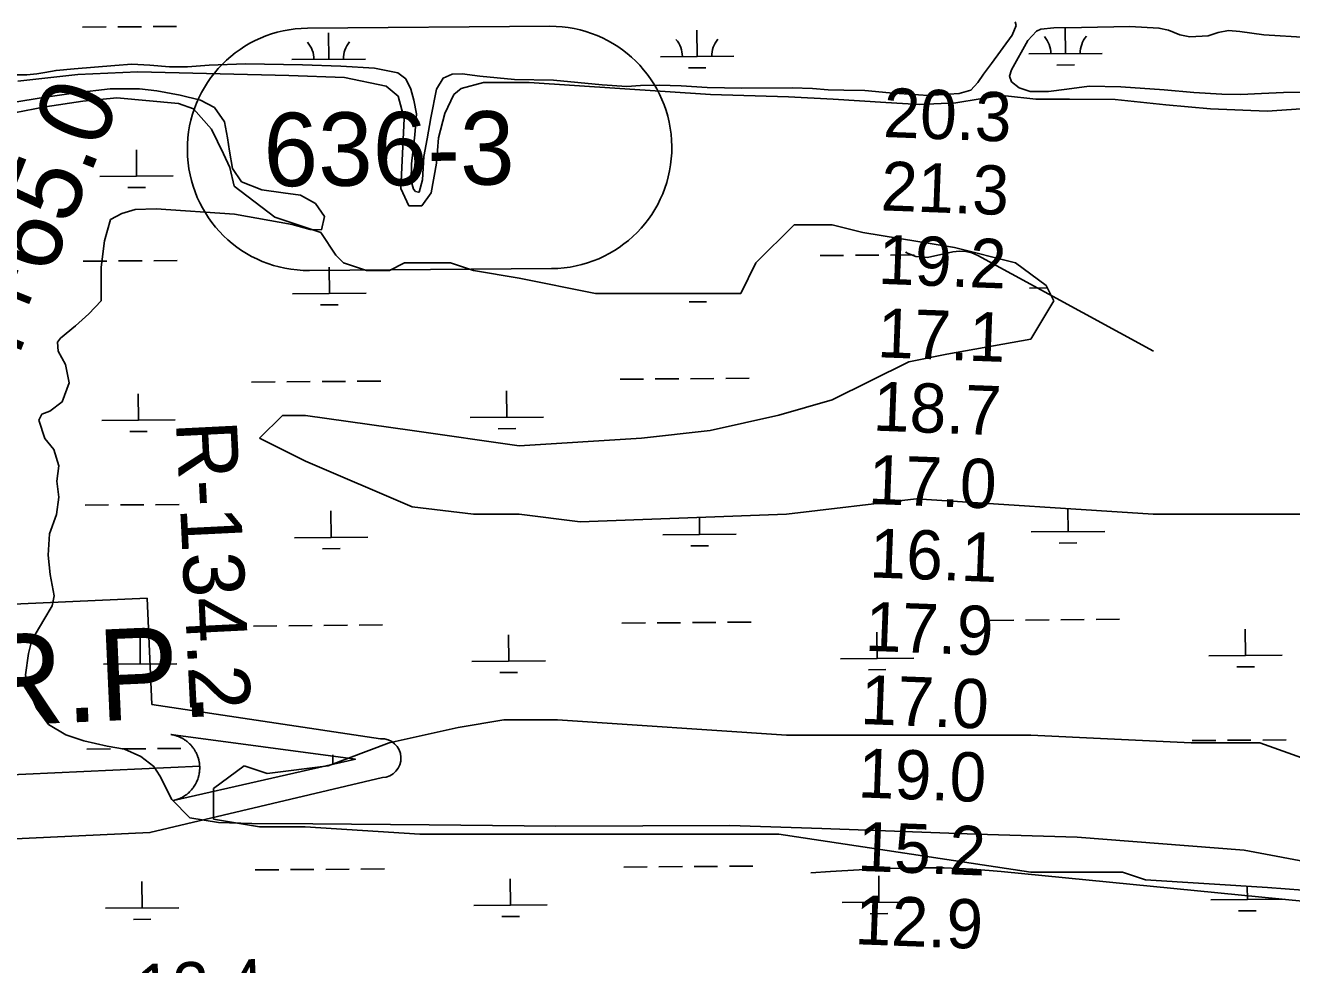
# Model space of a CAD drawing. Extents: x 3540316 to 3578335, y 553172 to 578787.
# Drawn here: x 3545537 to 3547262, y 567214 to 568493 of the extents above; entities that cross this region are included whole.
import ezdxf

# ---------------------------------------------------------------- set-up
doc = ezdxf.new("R2010")
doc.units = 0
for name, color, linetype in [('V-RIVR-RANG', 7, 'Continuous'), ('V-RIVR-RANG-IDEN', 7, 'Continuous'), ('V-ROAD-IDEN', 7, 'Continuous'), ('V-SITE-VEGE', 7, 'Continuous'), ('V-SURV-IDEN', 7, 'Continuous'), ('V-TOPO-MINR', 7, 'Continuous'), ('V-TOPO-WATR-IDEN', 7, 'Continuous'), ('V-WETL-SWMP', 7, 'Continuous')]:
    doc.layers.add(name, color=color, linetype=linetype)

msp = doc.modelspace()

# ---------------------------------------------------------------- linework, layer by layer
at = {"layer": 'V-ROAD-IDEN'}
for p, q in [((3545921.8, 568489.1), (3546251.8, 568491.7)), ((3545921.8, 568489.1), (3546251.8, 568491.7)), ((3545921.8, 568489.1), (3545921.8, 568489.1)), ((3546254.3, 568161.7), (3545924.3, 568159.1)), ((3546254.3, 568161.7), (3545924.3, 568159.1))]:
    msp.add_line(p, q, dxfattribs=at)
for centre, start, end in [((3546253.1, 568326.7), 270.4418, 90.4418), ((3546253.1, 568326.7), 270.4418, 90.4418), ((3545923.1, 568324.1), 90.4418, 270.4418), ((3545923.1, 568324.1), 90.4418, 270.4418)]:
    msp.add_arc(centre, 165, start, end, dxfattribs=at)
at = {"layer": 'V-SITE-VEGE'}
for p, q in [((3545527.3, 568416.9), (3545608.9, 568426.2)), ((3545608.9, 568426.2), (3545690.4, 568429.9)), ((3545690.4, 568429.9), (3545896.2, 568424.9)), ((3545896.2, 568424.9), (3545972.2, 568421.8)), ((3545972.2, 568421.8), (3546028.8, 568410.4)), ((3545653, 568406.6), (3545606, 568401.3)), ((3545693.1, 568406.4), (3545653, 568406.6)), ((3545716.5, 568403.6), (3545693.1, 568406.4)), ((3545748.3, 568397.9), (3545716.5, 568403.6)), ((3546028.8, 568410.4), (3546045.3, 568396.6)), ((3546121.3, 568399), (3546131, 568407.2)), ((3546131, 568407.2), (3546161.4, 568415.4)), ((3546161.4, 568415.4), (3546223.6, 568415.1)), ((3546223.6, 568415.1), (3546470.7, 568398.8)), ((3545561.8, 568394.6), (3545520.3, 568387.9)), ((3545606, 568401.3), (3545561.8, 568394.6)), ((3545775.9, 568390.9), (3545748.3, 568397.9)), ((3545795.2, 568381.1), (3545775.9, 568390.9)), ((3546045.3, 568396.6), (3546053.4, 568366.1)), ((3546108.7, 568372.8), (3546121.3, 568399)), ((3546470.7, 568398.8), (3546577.1, 568395.5)), ((3546577.1, 568395.5), (3546637.9, 568392.5)), ((3546637.9, 568392.5), (3546709.7, 568388)), ((3546709.7, 568388), (3546755.2, 568385)), ((3546755.2, 568385), (3546805, 568387.6)), ((3546805, 568387.6), (3546838.2, 568392.9)), ((3546838.2, 568392.9), (3546854.7, 568395.6)), ((3546854.7, 568395.6), (3546872.7, 568396.9)), ((3546872.7, 568396.9), (3546914.1, 568392.6)), ((3546914.1, 568392.6), (3546959.7, 568392.4)), ((3546959.7, 568392.4), (3547021.9, 568392.1)), ((3547021.9, 568392.1), (3547090.9, 568384.9)), ((3545808.9, 568361.7), (3545795.2, 568381.1)), ((3546100.3, 568339.7), (3546108.7, 568372.8)), ((3547090.9, 568384.9), (3547151.7, 568379.1)), ((3547151.7, 568379.1), (3547229, 568376)), ((3547229, 568376), (3547302.2, 568381.2)), ((3545812.9, 568339.6), (3545808.9, 568361.7)), ((3546053.4, 568366.1), (3546048.8, 568270.8)), ((3545815.6, 568321.6), (3545812.9, 568339.6)), ((3546097.3, 568305.1), (3546100.3, 568339.7)), ((3545819.7, 568298.1), (3545815.6, 568321.6)), ((3546090.3, 568265.1), (3546097.3, 568305.1)), ((3545832, 568280.1), (3545819.7, 568298.1)), ((3545859.6, 568268.9), (3545832, 568280.1)), ((3545888.6, 568264.7), (3545859.6, 568268.9)), ((3546048.8, 568270.8), (3546059.8, 568247.3)), ((3546077.7, 568247.2), (3546090.3, 568265.1)), ((3545912, 568261.8), (3545888.6, 568264.7)), ((3545932.7, 568250.6), (3545912, 568261.8)), ((3545945.1, 568232.6), (3545932.7, 568250.6)), ((3545653.6, 568228.4), (3545668.8, 568236.6)), ((3545668.8, 568236.6), (3545686.8, 568242.1)), ((3545686.8, 568242.1), (3545715.8, 568243.3)), ((3545715.8, 568243.3), (3545822.1, 568235.9)), ((3545822.1, 568235.9), (3545900.8, 568221.8)), ((3545940.8, 568214.7), (3545945.1, 568232.6)), ((3546059.8, 568247.3), (3546077.7, 568247.2)), ((3545645.2, 568199.5), (3545653.6, 568228.4)), ((3545900.8, 568221.8), (3545925.6, 568214.8)), ((3545925.6, 568214.8), (3545940.8, 568214.7)), ((3545640.8, 568163.6), (3545645.2, 568199.5)), ((3545640.8, 568142.8), (3545640.8, 568163.6)), ((3545640.6, 568118), (3545640.8, 568142.8)), ((3545624, 568100.1), (3545640.6, 568118)), ((3545605.9, 568083.6), (3545624, 568100.1)), ((3545585.2, 568067.1), (3545605.9, 568083.6)), ((3545581, 568061.6), (3545585.2, 568067.1)), ((3545582.3, 568049.2), (3545581, 568061.6)), ((3545591.9, 568031.2), (3545582.3, 568049.2)), ((3545597.3, 568006.3), (3545591.9, 568031.2)), ((3545587.5, 567980.1), (3545597.3, 568006.3)), ((3545570.9, 567967.7), (3545587.5, 567980.1)), ((3545555.6, 567955.4), (3545559.8, 567963.6)), ((3545563.8, 567930.5), (3545555.6, 567955.4)), ((3545559.8, 567963.6), (3545570.9, 567967.7)), ((3545576.2, 567915.2), (3545563.8, 567930.5)), ((3545583, 567893.1), (3545576.2, 567915.2)), ((3545580.1, 567872.4), (3545583, 567893.1)), ((3545582.8, 567850.3), (3545580.1, 567872.4)), ((3545579.9, 567826.8), (3545582.8, 567850.3)), ((3545570.1, 567800.6), (3545579.9, 567826.8)), ((3545568.6, 567771.6), (3545570.1, 567800.6)), ((3545571.3, 567745.3), (3545568.6, 567771.6)), ((3545576.6, 567716.3), (3545571.3, 567745.3)), ((3545573.8, 567702.5), (3545576.6, 567716.3)), ((3545562.7, 567683.2), (3545573.8, 567702.5)), ((3545546, 567655.7), (3545562.7, 567683.2)), ((3545541.8, 567637.7), (3545546, 567655.7)), ((3545537.5, 567608.7), (3545541.8, 567637.7)), ((3545541.5, 567589.4), (3545537.5, 567608.7)), ((3545552.5, 567563.1), (3545541.5, 567589.4)), ((3545568.9, 567540.9), (3545552.5, 567563.1)), ((3545592.4, 567527), (3545568.9, 567540.9)), ((3545617.2, 567518.6), (3545592.4, 567527)), ((3545648.9, 567511.5), (3545617.2, 567518.6)), ((3545672.4, 567507.3), (3545648.9, 567511.5)), ((3545694.5, 567497.5), (3545672.4, 567507.3)), ((3545712.3, 567483.6), (3545694.5, 567497.5)), ((3545720.6, 567471.1), (3545712.3, 567483.6)), ((3545737, 567438.6), (3545720.6, 567471.1)), ((3545761.3, 567413.8), (3545737, 567438.6)), ((3545800.6, 567407.6), (3545761.3, 567413.8)), ((3545845.7, 567406.2), (3545800.6, 567407.6)), ((3545929.2, 567405.4), (3545845.7, 567406.2)), ((3546087.3, 567404), (3545929.2, 567405.4)), ((3546260.2, 567402.5), (3546087.3, 567404)), ((3546496.9, 567403.3), (3546260.2, 567402.5)), ((3546622.6, 567399.2), (3546496.9, 567403.3)), ((3546832.7, 567391.5), (3546622.6, 567399.2)), ((3546970.2, 567387.3), (3546832.7, 567391.5)), ((3547197.9, 567369.6), (3546970.2, 567387.3)), ((3547309.7, 567348.9), (3547197.9, 567369.6))]:
    msp.add_line(p, q, dxfattribs=at)
at = {"layer": 'V-TOPO-MINR'}
for points in [[(3547074, 568049.1), (3546835, 568179.6), (3546826.8, 568183), (3546818.4, 568185.2), (3546809.8, 568185.5), (3546800.9, 568184.5), (3546766.2, 568177), (3546750.6, 568178.2), (3546737.8, 568183.3), (3546736.9, 568184.4)], [(3548007.1, 567208.3), (3547986.8, 567215.2), (3547966.4, 567221.5), (3547945.6, 567227), (3547924.7, 567231.9), (3547903.7, 567235.9), (3547882.5, 567239.5), (3547861.3, 567242.5), (3547840, 567244.9), (3546866.5, 567340.8), (3546827.9, 567343.8), (3546789.2, 567345.7), (3546750.5, 567345.8), (3546711.8, 567344.9), (3546673.1, 567342.9), (3546634.4, 567340.7), (3546607.3, 567338.8)]]:
    msp.add_lwpolyline(points, dxfattribs=at)
at = {"layer": 'V-TOPO-WATR-IDEN'}
msp.add_line((3545024.4, 567450.2), (3545774.9, 567483.9), dxfattribs=at)
for points in [[(3544775.5, 567465.6), (3545071.8, 567539.6), (3545065.4, 567684.2), (3545703.2, 567712.9), (3545709.7, 567568.3), (3546021.4, 567521.5)], [(3546023.8, 567468.6), (3545707, 567393.6), (3545503.8, 567384.4), (3545510.7, 567229.3), (3545321.8, 567220.8), (3545314.9, 567376), (3545090.3, 567365.9), (3544777.9, 567412.6)]]:
    msp.add_lwpolyline(points, dxfattribs=at)
msp.add_lwpolyline([(3545735.4, 567527.2), (3545987, 567493.5), (3545739.4, 567437.3), (3545743.8, 567438.5), (3545747.9, 567440.1), (3545749.5, 567440.9), (3545750.9, 567441.6), (3545752.6, 567442.6), (3545754.1, 567443.5), (3545755.4, 567444.4), (3545757.2, 567445.7), (3545759, 567447.2), (3545759.9, 567448), (3545761.2, 567449.2), (3545762.7, 567450.8), (3545763.9, 567452.1), (3545765, 567453.5), (3545765.8, 567454.4), (3545766.6, 567455.5), (3545767.5, 567456.9), (3545768.3, 567458.2), (3545769, 567459.5), (3545769.6, 567460.5), (3545770.5, 567462.2), (3545771.2, 567463.8), (3545771.7, 567465.1), (3545772.3, 567466.6), (3545772.8, 567468), (3545773.1, 567469.2), (3545773.4, 567470.2), (3545773.7, 567471.6), (3545774.1, 567473.1), (3545774.3, 567474.6), (3545774.5, 567476.1), (3545774.7, 567477.4), (3545774.8, 567478.9), (3545774.9, 567480.2), (3545774.9, 567481.9), (3545774.9, 567483.9), (3545774.8, 567484.6), (3545774.8, 567485.5), (3545774.7, 567486.6), (3545774.5, 567487.6), (3545774.4, 567488.7), (3545774.2, 567489.7), (3545774, 567490.8), (3545773.9, 567491.6), (3545773.6, 567492.8), (3545773.3, 567493.9), (3545773.1, 567494.7), (3545772.5, 567496.6), (3545772.1, 567497.6), (3545771.9, 567498.3), (3545771.4, 567499.4), (3545771, 567500.4), (3545770.5, 567501.5), (3545769.9, 567502.7), (3545769.3, 567503.8), (3545768.8, 567504.7), (3545768.4, 567505.4), (3545767.8, 567506.4), (3545767.2, 567507.2), (3545766.6, 567508.2), (3545765.9, 567509.2), (3545765.1, 567510.2), (3545764.1, 567511.4), (3545763.4, 567512.2), (3545762.6, 567513.1), (3545761.7, 567514), (3545761.1, 567514.7), (3545760.3, 567515.4), (3545759.1, 567516.4), (3545759.1, 567516.5), (3545758.4, 567517.1), (3545757.8, 567517.5), (3545757, 567518.2), (3545756, 567518.9), (3545755.1, 567519.5), (3545754.4, 567520), (3545753.4, 567520.7), (3545752.4, 567521.3), (3545751.7, 567521.7), (3545750.8, 567522.2), (3545749.5, 567522.9), (3545748.7, 567523.2), (3545748.1, 567523.5), (3545747.5, 567523.8), (3545746.8, 567524.1), (3545745.9, 567524.4), (3545745, 567524.8), (3545744.1, 567525.1), (3545743.2, 567525.4), (3545742, 567525.8), (3545741.3, 567526), (3545740.1, 567526.3), (3545738.8, 567526.6), (3545737.8, 567526.8), (3545737, 567526.9), (3545736.3, 567527.1), (3545735.7, 567527.1)], close=True, dxfattribs=at)
msp.add_arc((3546022.6, 567495), 26.5, 272.5722, 92.5722, dxfattribs=at)
at = {"layer": 'V-WETL-SWMP'}
for p, q in [((3545615.4, 568490.5), (3545647.4, 568490.8)), ((3545663.4, 568490.9), (3545695.4, 568491.1)), ((3545711.4, 568491.3), (3545743.4, 568491.5)), ((3546954.4, 568454.4), (3546954.1, 568490)), ((3545950.6, 568446.7), (3545950.3, 568482.7)), ((3546452.5, 568450.5), (3546452.2, 568486.5)), ((3546904.4, 568454), (3547004.4, 568454.8)), ((3545900.6, 568446.3), (3546000.6, 568447.1)), ((3546402.5, 568450.2), (3546502.5, 568450.9)), ((3546942.5, 568438.9), (3546966.5, 568439.1)), ((3546440.6, 568435), (3546464.6, 568435.2)), ((3545564.5, 568382.2), (3545615.8, 568389.6)), ((3545615.8, 568389.6), (3545662.2, 568394.1)), ((3545662.2, 568394.1), (3545745.9, 568386.5)), ((3545745.9, 568386.5), (3545766.5, 568379.4)), ((3545522.1, 568373.7), (3545564.5, 568382.2)), ((3545766.5, 568379.4), (3545790.9, 568351.7)), ((3545790.9, 568351.7), (3545807.3, 568318.2)), ((3545688.9, 568287.5), (3545688.6, 568323.5)), ((3545807.3, 568318.2), (3545816, 568299.4)), ((3545816, 568299.4), (3545821.7, 568273.9)), ((3545638.9, 568287.1), (3545738.9, 568287.9)), ((3545677, 568272), (3545701, 568272.2)), ((3545821.7, 568273.9), (3545877.3, 568231.6)), ((3545877.3, 568231.6), (3545939.7, 568210.9)), ((3546532.7, 568169.5), (3546584.7, 568221.4)), ((3546584.7, 568221.4), (3546636.7, 568221.4)), ((3546636.7, 568221.4), (3546678.3, 568211)), ((3545939.7, 568210.9), (3545960.5, 568179.8)), ((3546678.3, 568211), (3546803.2, 568190.3)), ((3545960.5, 568179.8), (3545970.9, 568169.4)), ((3546620.1, 568179.4), (3546652.1, 568179.7)), ((3546668.1, 568179.8), (3546700.1, 568180.1)), ((3546716.1, 568180.2), (3546748.1, 568180.4)), ((3546803.2, 568190.3), (3546886.4, 568169.6)), ((3545616.3, 568171.7), (3545648.3, 568171.9)), ((3545664.3, 568172.1), (3545696.3, 568172.3)), ((3545712.3, 568172.4), (3545744.3, 568172.7)), ((3545951.5, 568127.9), (3545951.2, 568163.9)), ((3545970.9, 568169.4), (3546002.1, 568159)), ((3546033.3, 568159), (3546054.1, 568169.4)), ((3546054.1, 568169.4), (3546116.5, 568169.4)), ((3546116.5, 568169.4), (3546147.7, 568159.1)), ((3546511.9, 568128), (3546532.7, 568169.5)), ((3546886.4, 568169.6), (3546928, 568138.5)), ((3546002.1, 568159), (3546033.3, 568159)), ((3546147.7, 568159.1), (3546210.2, 568148.7)), ((3546210.2, 568148.7), (3546314.2, 568128)), ((3545901.5, 568127.5), (3546001.5, 568128.3)), ((3546314.2, 568128), (3546387, 568128)), ((3546387, 568128), (3546511.9, 568128)), ((3546905.3, 568135.3), (3546929.5, 568135.5)), ((3546928, 568138.5), (3546938.4, 568117.7)), ((3545939.6, 568112.4), (3545963.6, 568112.6)), ((3546441.5, 568116.3), (3546465.5, 568116.5)), ((3546938.4, 568117.7), (3546907.2, 568065.8)), ((3546907.2, 568065.8), (3546792.8, 568045.1)), ((3546792.8, 568045.1), (3546740.7, 568034.7)), ((3546740.7, 568034.7), (3546636.7, 567982.8)), ((3545845.6, 568007.2), (3545877.6, 568007.4)), ((3545893.6, 568007.6), (3545925.6, 568007.8)), ((3545941.6, 568007.9), (3545973.6, 568008.2)), ((3545989.6, 568008.3), (3546021.6, 568008.6)), ((3546347.5, 568011.1), (3546379.5, 568011.3)), ((3546395.5, 568011.4), (3546427.5, 568011.7)), ((3546443.5, 568011.8), (3546475.5, 568012.1)), ((3546491.5, 568012.2), (3546523.5, 568012.4)), ((3545691.4, 567955.3), (3545691.1, 567991.3)), ((3546193.3, 567959.2), (3546193, 567995.2)), ((3546636.7, 567982.8), (3546563.9, 567962)), ((3545641.4, 567954.9), (3545741.4, 567955.7)), ((3545887.6, 567961.9), (3545856.4, 567930.8)), ((3545918.8, 567961.9), (3545887.6, 567961.9)), ((3546064.5, 567941.2), (3545918.8, 567961.9)), ((3546143.3, 567958.8), (3546243.3, 567959.6)), ((3546563.9, 567962), (3546470.2, 567941.3)), ((3545679.5, 567939.8), (3545703.5, 567940)), ((3546210.1, 567920.5), (3546064.5, 567941.2)), ((3546181.4, 567943.7), (3546205.4, 567943.9)), ((3546470.2, 567941.3), (3546376.6, 567930.9)), ((3545856.4, 567930.8), (3545918.8, 567899.7)), ((3546376.6, 567930.9), (3546210.1, 567920.5)), ((3545918.8, 567899.7), (3546064.5, 567837.5)), ((3545618.8, 567839.5), (3545650.8, 567839.8)), ((3545666.8, 567839.9), (3545698.8, 567840.1)), ((3545714.8, 567840.2), (3545746.8, 567840.5)), ((3546064.5, 567837.5), (3546147.7, 567827.1)), ((3546574.2, 567827.2), (3546751.1, 567848)), ((3546751.1, 567848), (3547073.6, 567827.3)), ((3546957.8, 567803.5), (3546957.6, 567834.7)), ((3545954, 567795.7), (3545953.7, 567831.7)), ((3546147.7, 567827.1), (3546210.1, 567827.1)), ((3546210.1, 567827.1), (3546293.3, 567816.7)), ((3546293.3, 567816.7), (3546574.2, 567827.2)), ((3546455.9, 567799.6), (3546455.7, 567822.8)), ((3547073.6, 567827.3), (3547156.8, 567827.3)), ((3547156.8, 567827.3), (3547292.1, 567827.3)), ((3546405.9, 567799.2), (3546505.9, 567800)), ((3546907.8, 567803.1), (3547007.8, 567803.8)), ((3545904, 567795.3), (3546004, 567796.1)), ((3546444, 567784.1), (3546468, 567784.3)), ((3546945.9, 567788), (3546969.9, 567788.1)), ((3545942.1, 567780.2), (3545966.1, 567780.4)), ((3546350, 567678.9), (3546382, 567679.1)), ((3546398, 567679.2), (3546430, 567679.5)), ((3546446, 567679.6), (3546478, 567679.9)), ((3546494, 567680), (3546526, 567680.2)), ((3546851.9, 567682.7), (3546883.9, 567683)), ((3546899.9, 567683.1), (3546931.9, 567683.4)), ((3546947.9, 567683.5), (3546979.9, 567683.7)), ((3546995.9, 567683.9), (3547027.9, 567684.1)), ((3545848.1, 567675), (3545880.1, 567675.2)), ((3545896.1, 567675.4), (3545928.1, 567675.6)), ((3545944.1, 567675.7), (3545976.1, 567676)), ((3545992.1, 567676.1), (3546024.1, 567676.4)), ((3546195.8, 567627), (3546195.5, 567663)), ((3546697.7, 567630.9), (3546697.4, 567666.8)), ((3547199.5, 567634.7), (3547199.3, 567670.7)), ((3545693.9, 567623.1), (3545693.6, 567659.1)), ((3546145.8, 567626.6), (3546245.8, 567627.4)), ((3546647.7, 567630.5), (3546747.7, 567631.3)), ((3547149.5, 567634.4), (3547249.5, 567635.1)), ((3545643.9, 567622.8), (3545743.9, 567623.5)), ((3546183.9, 567611.5), (3546207.9, 567611.7)), ((3546685.8, 567615.4), (3546709.8, 567615.6)), ((3547187.7, 567619.2), (3547211.7, 567619.4)), ((3545682, 567607.6), (3545706, 567607.8)), ((3546189.2, 567547), (3546126.8, 567536.6)), ((3546262.1, 567547), (3546189.2, 567547)), ((3546574.2, 567526.3), (3546262.1, 567547)), ((3546126.8, 567536.6), (3546033.2, 567515.8)), ((3546907.1, 567526.4), (3546574.2, 567526.3)), ((3547125.6, 567516), (3546907.1, 567526.4)), ((3545621.3, 567507.3), (3545653.3, 567507.6)), ((3545669.3, 567507.7), (3545701.3, 567507.9)), ((3545717.3, 567508.1), (3545749.3, 567508.3)), ((3546033.2, 567515.8), (3545950, 567484.7)), ((3547219.2, 567516.1), (3547125.6, 567516)), ((3547127, 567518.9), (3547159, 567519.2)), ((3547175, 567519.3), (3547207, 567519.5)), ((3547333.6, 567474.6), (3547219.2, 567516.1)), ((3547223, 567519.7), (3547255, 567519.9)), ((3545956.3, 567487.1), (3545956.2, 567499.5)), ((3545835.5, 567484.7), (3545793.9, 567453.6)), ((3545866.7, 567474.3), (3545835.5, 567484.7)), ((3545950, 567484.7), (3545866.7, 567474.3)), ((3545793.9, 567453.6), (3545793.9, 567412.1)), ((3545793.9, 567412.1), (3545856.3, 567401.7)), ((3545856.3, 567401.7), (3545918.7, 567401.7)), ((3545918.7, 567401.7), (3546074.8, 567391.4)), ((3546074.8, 567391.4), (3546563.8, 567391.5)), ((3546563.8, 567391.5), (3546907.1, 567339.6)), ((3545850.6, 567342.8), (3545882.6, 567343.1)), ((3545898.6, 567343.2), (3545930.6, 567343.4)), ((3545946.6, 567343.6), (3545978.6, 567343.8)), ((3545994.6, 567343.9), (3546026.6, 567344.2)), ((3546352.5, 567346.7), (3546384.5, 567346.9)), ((3546400.5, 567347), (3546432.5, 567347.3)), ((3546448.5, 567347.4), (3546480.5, 567347.7)), ((3546496.5, 567347.8), (3546528.5, 567348)), ((3546700.2, 567298.7), (3546699.9, 567334.6)), ((3546907.1, 567339.6), (3547031.9, 567339.7)), ((3547031.9, 567339.7), (3547063.1, 567329.3)), ((3545696.4, 567291), (3545696.1, 567326.9)), ((3546198.3, 567294.8), (3546198, 567330.8)), ((3547063.1, 567329.3), (3547229.6, 567319)), ((3547202.1, 567302.6), (3547201.9, 567320.7)), ((3547229.6, 567319), (3547364.8, 567308.6)), ((3546650.2, 567298.3), (3546750.2, 567299.1)), ((3547152.1, 567302.2), (3547252.1, 567302.9)), ((3545646.4, 567290.6), (3545746.4, 567291.3)), ((3546148.3, 567294.4), (3546248.3, 567295.2)), ((3546688.3, 567283.2), (3546712.3, 567283.4)), ((3547190.2, 567287.1), (3547214.2, 567287.2)), ((3545684.5, 567275.4), (3545708.5, 567275.6)), ((3546186.4, 567279.3), (3546210.4, 567279.5))]:
    msp.add_line(p, q, dxfattribs=at)
for points in [[(3546886, 568497.6), (3546887.3, 568492.8), (3546881.8, 568479.8), (3546853.6, 568440.9), (3546842.6, 568426.6), (3546835, 568415), (3546825.4, 568404.8), (3546809.6, 568400.1), (3546767.2, 568397.6), (3546714.5, 568401.2), (3546681, 568404.1), (3546652.3, 568404.9), (3546631.1, 568405), (3546609.9, 568407.2), (3546581.9, 568408), (3546513.5, 568407.6), (3546466.3, 568408.5), (3546430.7, 568410.7), (3546400.6, 568411.5), (3546375.3, 568411), (3546356.8, 568409.7), (3546323.3, 568411.9), (3546257, 568418.4), (3546203.6, 568419.3), (3546156.5, 568423.6), (3546132.5, 568427.1), (3546118.9, 568426.5), (3546106.5, 568421.1), (3546097.6, 568406.1), (3546089.9, 568367.1), (3546084.9, 568338.4), (3546080, 568314.5), (3546078.5, 568282.4), (3546073.7, 568266), (3546073, 568266), (3546068.9, 568266.7), (3546066.2, 568270.1), (3546062.8, 568281.1), (3546063.6, 568304.3), (3546067.9, 568344), (3546070.1, 568372.7), (3546066.7, 568391.2), (3546062.7, 568406.2), (3546055.9, 568420), (3546045, 568428.2), (3546012.9, 568434.5), (3545967.1, 568437.5), (3545915.1, 568439.1), (3545837.1, 568440.8), (3545787.9, 568439), (3545758.4, 568436.4), (3545733.8, 568436.5), (3545707.1, 568438.6), (3545682.5, 568440.1), (3545659.3, 568438.2), (3545603.8, 568433.6), (3545579.2, 568431.7), (3545564.1, 568429), (3545553.2, 568427), (3545539.5, 568425.7), (3545525.8, 568425.8)], [(3547284.3, 568402), (3547251.5, 568401.5), (3547221.4, 568400.3), (3547193.3, 568399), (3547167.4, 568399.2), (3547129.1, 568401.4), (3547088.7, 568405), (3547029.9, 568409.4), (3546986.8, 568410.2), (3546956, 568406.3), (3546931.4, 568403), (3546906.1, 568403.1), (3546891, 568407.9), (3546880.8, 568416.2), (3546878.1, 568423.7), (3546880.9, 568432.6), (3546903, 568472.2), (3546914.7, 568485.1), (3546920.8, 568487.8), (3546938.6, 568489.8), (3546976.2, 568490.3), (3547041.9, 568491.4), (3547081.6, 568489.2), (3547094.6, 568486.4), (3547110.3, 568480.1), (3547123.9, 568477.3), (3547148.6, 568478.6), (3547162.3, 568483.3), (3547176.6, 568486), (3547191.7, 568484.6), (3547224.5, 568480.3), (3547284, 568476.6)]]:
    msp.add_lwpolyline(points, dxfattribs=at)
for centre, start, end in [((3546397.2, 568450.6), 359.6699, 41.2135), ((3546507.7, 568451.4), 139.6699, 181.2135), ((3546899.1, 568454.5), 359.6699, 41.2135), ((3547009.6, 568455.3), 139.6699, 181.2135), ((3545895.3, 568446.7), 359.6699, 41.2135), ((3546005.8, 568447.6), 139.6699, 181.2135)]:
    msp.add_arc(centre, 35.2, start, end, dxfattribs=at)

# ---------------------------------------------------------------- texts
at = {"layer": 'V-RIVR-RANG'}
for s, rotation, p in [('20.3', 357.8383, (3546705.4, 568341)), ('21.3', 357.8383, (3546701.9, 568241.1)), ('19.2', 357.8383, (3546698.3, 568141.1)), ('17.1', 357.8383, (3546697.2, 568041.1)), ('18.7', 357.8383, (3546691.3, 567941.2)), ('17.0', 357.8383, (3546684.9, 567841.4)), ('16.1', 357.8383, (3546686.6, 567741.3)), ('17.9', 357.8383, (3546680.5, 567641.4)), ('17.0', 357.8383, (3546674.3, 567541.6)), ('19.0', 357.8383, (3546670.8, 567441.7)), ('15.2', 357.8383, (3546670.2, 567341.6)), ('12.9', 357.8383, (3546666.4, 567241.7)), ('13.4', 2.7083, (3545690.3, 567146.9))]:
    msp.add_text(s, height=67, rotation=rotation, dxfattribs=at).set_placement(p)
at = {"layer": 'V-RIVR-RANG-IDEN'}
msp.add_text('R-134.2', height=83, rotation=272.8481, dxfattribs=at).set_placement((3545742.4, 567952.9))
at = {"layer": 'V-ROAD-IDEN'}
msp.add_text('636-3', height=100, rotation=0.4418, dxfattribs=at).set_placement((3545862.1, 568273.7))
at = {"layer": 'V-SURV-IDEN'}
msp.add_text('4864+65.0', height=100, rotation=68.3739, dxfattribs=at).set_placement((3545432.3, 567800.3))
at = {"layer": 'V-TOPO-WATR-IDEN'}
msp.add_text('L.W.R.P.', height=124.5, rotation=2.5721, dxfattribs=at).set_placement((3545130.4, 567522.5))

doc.saveas('drawing.dxf')
